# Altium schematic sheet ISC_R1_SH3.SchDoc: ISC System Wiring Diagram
size B; DrawnBy: Filiberto Clara; Engineer: Filiberto Clara; Organization: LIGO Laboratory; Address1: California Institute of Technology; Address2: Massachusetts Institute of Technology; SheetNumber: 12; SheetTotal: 37
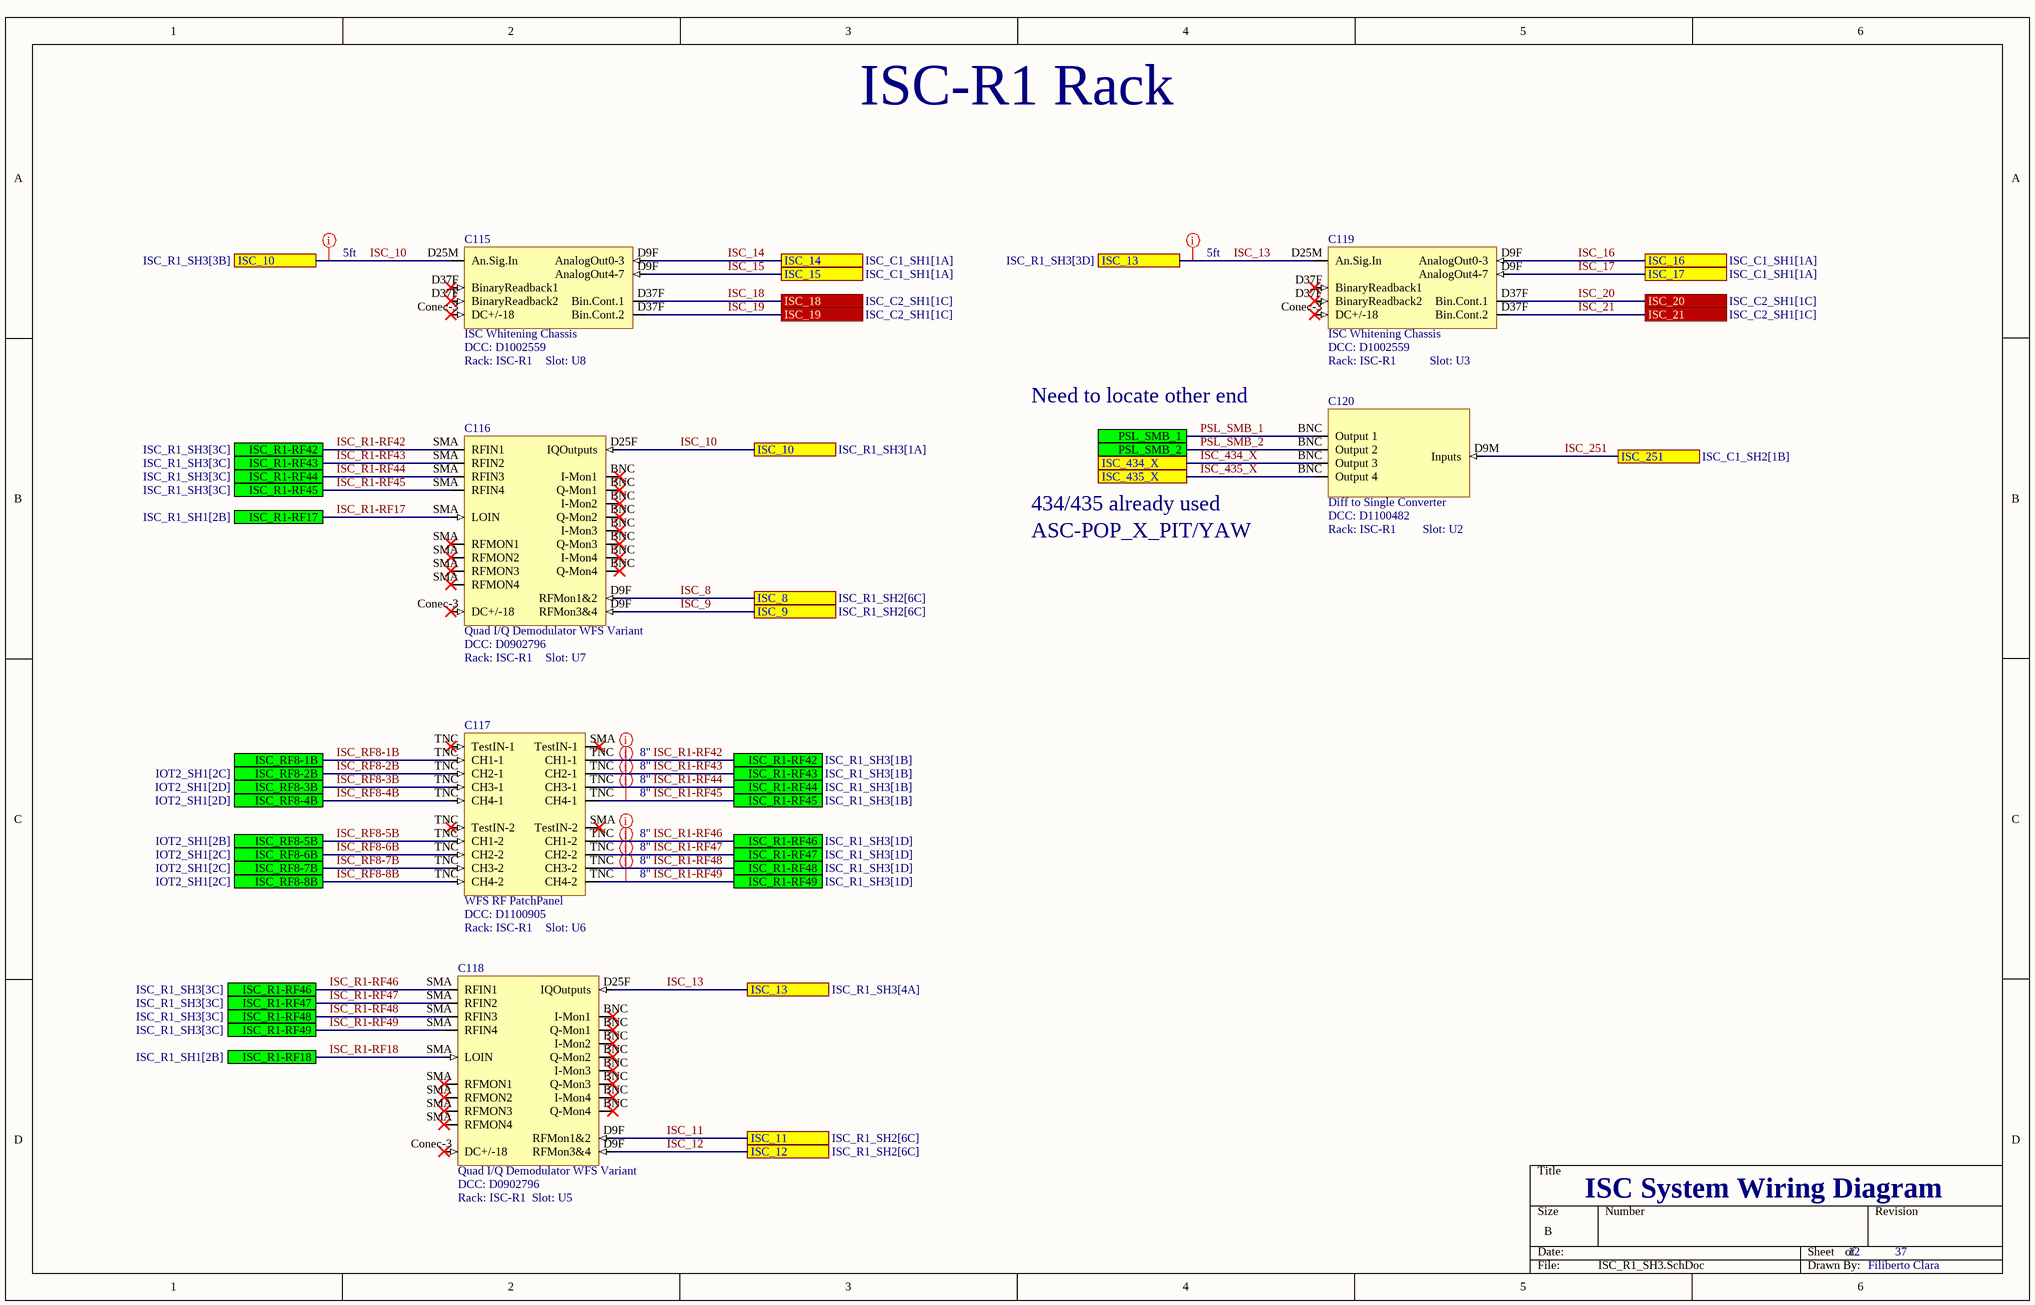
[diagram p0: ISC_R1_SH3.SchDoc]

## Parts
C115  ISC Whitening Chassis  DCC: D1002559  Rack: ISC-R1  Slot: U8
C116  Quad I/Q Demodulator WFS Variant  DCC: D0902796  Rack: ISC-R1  Slot: U7
C117  WFS RF PatchPanel  DCC: D1100905  Rack: ISC-R1  Slot: U6
C118  Quad I/Q Demodulator WFS Variant  DCC: D0902796  Rack: ISC-R1  Slot: U5
C119  ISC Whitening Chassis  DCC: D1002559  Rack: ISC-R1  Slot: U3
C120  Diff to Single Converter  DCC: D1100482  Rack: ISC-R1  Slot: U2

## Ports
ISC_8 (see ISC_R1_SH2[6C]), ISC_9 (see ISC_R1_SH2[6C]), ISC_10 (see ISC_R1_SH3[1A]), ISC_10 (see ISC_R1_SH3[3B]), ISC_11 (see ISC_R1_SH2[6C]), ISC_12 (see ISC_R1_SH2[6C]), ISC_13 (see ISC_R1_SH3[3D]), ISC_13 (see ISC_R1_SH3[4A]), ISC_14 (see ISC_C1_SH1[1A]), ISC_15 (see ISC_C1_SH1[1A]), ISC_16 (see ISC_C1_SH1[1A]), ISC_17 (see ISC_C1_SH1[1A]), ISC_18 (see ISC_C2_SH1[1C]), ISC_19 (see ISC_C2_SH1[1C]), ISC_20 (see ISC_C2_SH1[1C]), ISC_21 (see ISC_C2_SH1[1C]), ISC_251 (see ISC_C1_SH2[1B]), ISC_434_X, ISC_435_X, ISC_R1-RF17 (see ISC_R1_SH1[2B]), ISC_R1-RF18 (see ISC_R1_SH1[2B]), ISC_R1-RF42 (see ISC_R1_SH3[1B]), ISC_R1-RF42 (see ISC_R1_SH3[3C]), ISC_R1-RF43 (see ISC_R1_SH3[1B]), ISC_R1-RF43 (see ISC_R1_SH3[3C]), ISC_R1-RF44 (see ISC_R1_SH3[1B]), ISC_R1-RF44 (see ISC_R1_SH3[3C]), ISC_R1-RF45 (see ISC_R1_SH3[1B]), ISC_R1-RF45 (see ISC_R1_SH3[3C]), ISC_R1-RF46 (see ISC_R1_SH3[1D]), ISC_R1-RF46 (see ISC_R1_SH3[3C]), ISC_R1-RF47 (see ISC_R1_SH3[1D]), ISC_R1-RF47 (see ISC_R1_SH3[3C]), ISC_R1-RF48 (see ISC_R1_SH3[1D]), ISC_R1-RF48 (see ISC_R1_SH3[3C]), ISC_R1-RF49 (see ISC_R1_SH3[1D]), ISC_R1-RF49 (see ISC_R1_SH3[3C]), ISC_RF8-1B, ISC_RF8-2B (see IOT2_SH1[2C]), ISC_RF8-3B (see IOT2_SH1[2D]), ISC_RF8-4B (see IOT2_SH1[2D]), ISC_RF8-5B (see IOT2_SH1[2B]), ISC_RF8-6B (see IOT2_SH1[2C]), ISC_RF8-7B (see IOT2_SH1[2C]), ISC_RF8-8B (see IOT2_SH1[2C]), PSL_SMB_1, PSL_SMB_2

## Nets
ISC_8: C116.D9F(RFMon1&2) ; port ISC_8
ISC_9: C116.D9F(RFMon3&4) ; port ISC_9
ISC_10: C115.D25M(An.Sig.In) C116.D25F(IQOutputs) ; port ISC_10
ISC_11: C118.D9F(RFMon1&2) ; port ISC_11
ISC_12: C118.D9F(RFMon3&4) ; port ISC_12
ISC_13: C118.D25F(IQOutputs) C119.D25M(An.Sig.In) ; port ISC_13
ISC_14: C115.D9F(AnalogOut0-3) ; port ISC_14
ISC_15: C115.D9F(AnalogOut4-7) ; port ISC_15
ISC_16: C119.D9F(AnalogOut0-3) ; port ISC_16
ISC_17: C119.D9F(AnalogOut4-7) ; port ISC_17
ISC_18: C115.D37F(BinaryReadback1) ; port ISC_18
ISC_19: C115.D37F(Bin.Cont.2) ; port ISC_19
ISC_20: C119.D37F(BinaryReadback1) ; port ISC_20
ISC_21: C119.D37F(Bin.Cont.2) ; port ISC_21
ISC_251: C120.D9M(Inputs) ; port ISC_251
ISC_434_X: C120.BNC(Output_3) ; port ISC_434_X
ISC_435_X: C120.BNC(Output_4) ; port ISC_435_X
ISC_R1-RF17: C116.SMA(LOIN) ; port ISC_R1-RF17
ISC_R1-RF18: C118.SMA(LOIN) ; port ISC_R1-RF18
ISC_R1-RF42: C116.SMA(RFIN1) C117.TNC(CH1-1) ; port ISC_R1-RF42
ISC_R1-RF43: C116.SMA(RFIN2) C117.TNC(CH2-1) ; port ISC_R1-RF43
ISC_R1-RF44: C116.SMA(RFIN3) C117.TNC(CH3-1) ; port ISC_R1-RF44
ISC_R1-RF45: C116.SMA(RFIN4) C117.TNC(CH4-1) ; port ISC_R1-RF45
ISC_R1-RF46: C117.TNC(CH1-2) C118.SMA(RFIN1) ; port ISC_R1-RF46
ISC_R1-RF47: C117.TNC(CH2-2) C118.SMA(RFIN2) ; port ISC_R1-RF47
ISC_R1-RF48: C117.TNC(CH3-2) C118.SMA(RFIN3) ; port ISC_R1-RF48
ISC_R1-RF49: C117.TNC(CH4-2) C118.SMA(RFIN4) ; port ISC_R1-RF49
ISC_RF8-1B: C117.TNC(TestIN-1) ; port ISC_RF8-1B
ISC_RF8-2B: C117.TNC(CH2-1) ; port ISC_RF8-2B
ISC_RF8-3B: C117.TNC(CH3-1) ; port ISC_RF8-3B
ISC_RF8-4B: C117.TNC(CH4-1) ; port ISC_RF8-4B
ISC_RF8-5B: C117.TNC(CH1-2) ; port ISC_RF8-5B
ISC_RF8-6B: C117.TNC(CH2-2) ; port ISC_RF8-6B
ISC_RF8-7B: C117.TNC(CH3-2) ; port ISC_RF8-7B
ISC_RF8-8B: C117.TNC(CH4-2) ; port ISC_RF8-8B
PSL_SMB_1: C120.BNC(Output_1) ; port PSL_SMB_1
PSL_SMB_2: C120.BNC(Output_2) ; port PSL_SMB_2

Not connected (* = marked no-connect by the designer): C115 Conec-3(DC+/-18)*; C116 BNC(I-Mon1)* Conec-3(DC+/-18)*; C117 SMA(TestIN-1)*; C118 BNC(I-Mon1)* Conec-3(DC+/-18)*; C119 Conec-3(DC+/-18)*

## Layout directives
Length: 5ft: ISC_10, ISC_13
Length: 8": ISC_R1-RF42, ISC_R1-RF43, ISC_R1-RF44, ISC_R1-RF45, ISC_R1-RF46, ISC_R1-RF47, ISC_R1-RF48, ISC_R1-RF49

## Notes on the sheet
- ISC-R1 Rack
- (near C120) Need to locate other end
- 434/435 already used
- ASC-POP_X_PIT/YAW

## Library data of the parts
C115 C119 = ISC Whitening: Serial: Sxxxxxxx
C116 C118 = QuadIQdemod_WFS: Serial: Sxxxxxxx; System: ISC
C117 = WFS RFPD PatchPanel: Serial: Sxxxxxxx; System: ISC
C120 = Diff to Single Converter: Serial: Sxxxxxxx; System: ISC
